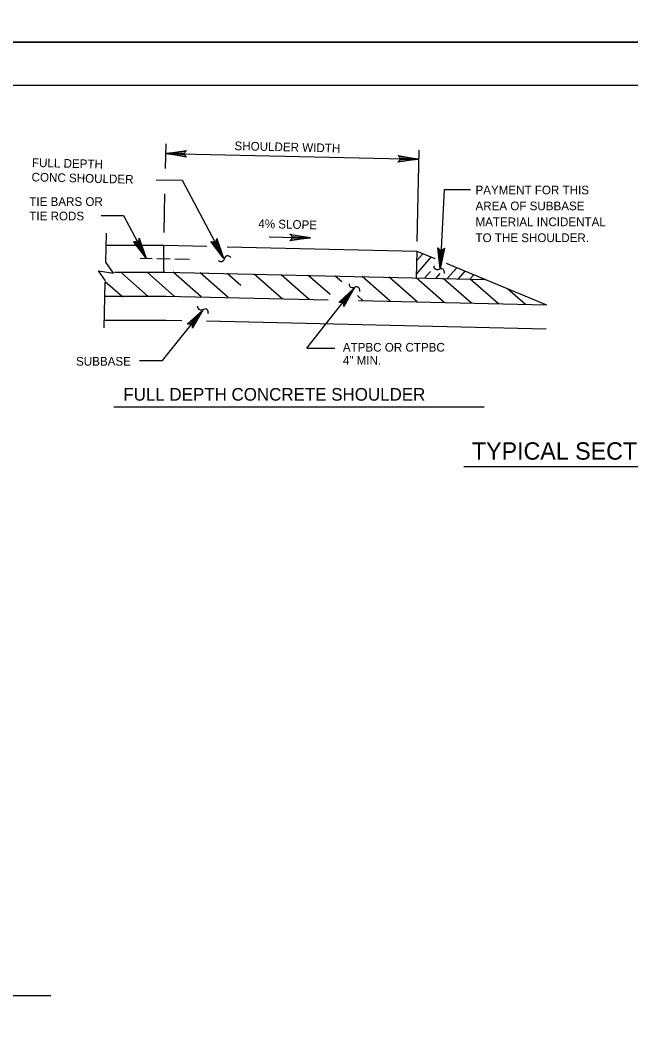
# Model space of a CAD drawing. Extents: x 638216 to 639962, y 297510 to 299292.
# Drawn here: x 638606.1 to 638817, y 297758.8 to 298111.7 of the extents above; entities that cross this region are included whole.
import ezdxf

# ---------------------------------------------------------------- set-up
doc = ezdxf.new("R2010")
doc.units = 0
for name, color, linetype in [('1', 7, 'Continuous'), ('2', 7, 'Continuous'), ('3', 7, 'Continuous'), ('PLT-BNDY', 7, 'Continuous')]:
    doc.layers.add(name, color=color, linetype=linetype)

msp = doc.modelspace()

# ---------------------------------------------------------------- linework, layer by layer
at = {"layer": '1'}
for p, q in [((638656.27, 298060.6), (638656.47, 298069.04)), ((638656.39, 298065.79), (638743.74, 298063.74)), ((638743.2, 298035.35), (638743.94, 298066.92)), ((638662.03, 298056.48), (638676.31, 298029.54)), ((638655.75, 298038.39), (638656.06, 298051.84)), ((638752.61, 298053.26), (638751.15, 298025.85)), ((638641.73, 298044.32), (638649.55, 298029.56)), ((638635.63, 298028.05), (638635.87, 298038.2)), ((638743.13, 298031.97), (638742.91, 298022.75)), ((638742.94, 298024.03), (638748.11, 298029.91)), ((638743.05, 298028.7), (638745.18, 298031.12)), ((638753.58, 298022.5), (638756.9, 298026.27)), ((638650.31, 298016.32), (638641.19, 298024.34)), ((638659.3, 298016.41), (638649.99, 298024.6)), ((638668.63, 298016.19), (638658.94, 298024.71)), ((638677.96, 298015.97), (638668.27, 298024.5)), ((638682.29, 298020.15), (638677.6, 298024.28)), ((638696.62, 298015.53), (638686.93, 298024.06)), ((638705.95, 298015.32), (638696.27, 298023.84)), ((638713.11, 298017.02), (638705.6, 298023.62)), ((638717.16, 298021.44), (638714.93, 298023.4)), ((638733.95, 298014.66), (638724.26, 298023.19)), ((638743.28, 298014.44), (638733.59, 298022.97)), ((638752.61, 298014.23), (638742.92, 298022.75)), ((638745.75, 298022.68), (638747.78, 298024.99)), ((638749.66, 298022.59), (638751.15, 298024.28)), ((638757.5, 298022.41), (638759.82, 298025.06)), ((638761.41, 298022.32), (638762.75, 298023.84)), ((638635.1, 298005.52), (638635.47, 298021.3)), ((638641.52, 298016.07), (638635.47, 298021.38)), ((638705.06, 297998.48), (638721.49, 298019.18)), ((638761.95, 298014.01), (638752.26, 298022.53)), ((638771.28, 298013.79), (638761.59, 298022.31)), ((638765.33, 298022.23), (638765.68, 298022.63)), ((638724.62, 298014.88), (638722.63, 298016.62)), ((638780.61, 298013.57), (638774.44, 298019)), ((638655.26, 297994.16), (638669.14, 298011.65))]:
    msp.add_line(p, q, dxfattribs=at)
for points in [[(639041.88, 297525.24), (639041.88, 298089.24), (638255.88, 298089.24), (638255.88, 297525.24), (639041.88, 297525.24), (639041.88, 297551.6), (638841.88, 297551.6), (638841.88, 297616.28), (639041.88, 297616.28), (639041.88, 297645.24), (638841.88, 297645.24), (638841.88, 297525.24), (638920.69, 297525.24), (638920.69, 297551.6), (638920.69, 297525.24), (638997.69, 297525.24), (638997.69, 297551.6), (638997.69, 297539.28), (639041.88, 297539.28)], [(639041.88, 297525.24), (639041.88, 298089.24), (638255.88, 298089.24), (638255.88, 297525.24), (639041.88, 297525.24), (639041.88, 297551.6), (638841.88, 297551.6), (638841.88, 297616.28), (639041.88, 297616.28), (639041.88, 297645.24), (638841.88, 297645.24), (638841.88, 297525.24), (638920.69, 297525.24), (638920.69, 297551.6), (638920.69, 297525.24), (638997.69, 297525.24), (638997.69, 297551.6), (638997.69, 297539.28), (639041.88, 297539.28)], [(639041.88, 297525.24), (639041.88, 298089.24), (638255.88, 298089.24), (638255.88, 297525.24), (639041.88, 297525.24), (639041.88, 297551.6), (638841.88, 297551.6), (638841.88, 297616.28), (639041.88, 297616.28), (639041.88, 297645.24), (638841.88, 297645.24), (638841.88, 297525.24), (638920.69, 297525.24), (638920.69, 297551.6), (638920.69, 297525.24), (638997.69, 297525.24), (638997.69, 297551.6), (638997.69, 297539.28), (639041.88, 297539.28)], [(638663.18, 298064.77), (638662.94, 298065.27), (638656.39, 298065.79), (638663.18, 298064.77), (638663.52, 298064.46), (638656.39, 298065.79), (638662.95, 298065.96), (638663.2, 298066.44), (638656.39, 298065.79), (638663.57, 298066.76), (638663.2, 298066.44)], [(638736.95, 298064.76), (638737.2, 298064.26), (638743.74, 298063.74), (638736.95, 298064.76), (638736.61, 298065.07), (638743.74, 298063.74), (638737.19, 298063.57), (638736.94, 298063.09), (638743.74, 298063.74), (638736.56, 298062.77), (638736.94, 298063.09)], [(638699.61, 298037.58), (638699.86, 298037.08), (638706.4, 298036.57), (638699.61, 298037.58), (638699.27, 298037.89), (638706.4, 298036.57), (638699.85, 298036.4), (638699.59, 298035.91), (638706.4, 298036.57), (638699.22, 298035.6), (638699.59, 298035.91)], [(638647.12, 298035.98), (638646.8, 298035.52), (638649.55, 298029.56), (638647.12, 298035.98), (638647.22, 298036.43), (638649.55, 298029.56), (638646.2, 298035.2), (638645.65, 298035.18), (638649.55, 298029.56), (638645.19, 298035.35), (638645.65, 298035.18)], [(638673.87, 298035.96), (638673.56, 298035.5), (638676.31, 298029.54), (638673.87, 298035.96), (638673.97, 298036.41), (638676.31, 298029.54), (638672.95, 298035.18), (638672.41, 298035.16), (638676.31, 298029.54), (638671.95, 298035.33), (638672.41, 298035.16)], [(638752.36, 298032.66), (638751.85, 298032.43), (638751.14, 298025.9), (638752.36, 298032.66), (638752.68, 298032.99), (638751.14, 298025.9), (638751.17, 298032.46), (638750.69, 298032.73), (638751.14, 298025.9), (638750.39, 298033.12), (638750.69, 298032.73)], [(638635.52, 298021.76), (638633.08, 298025.18), (638638.35, 298024.36), (638635.6, 298028.15)], [(638716.59, 298014.37), (638717.13, 298014.27), (638721.49, 298019.18), (638716.59, 298014.37), (638716.14, 298014.29), (638721.49, 298019.18), (638717.67, 298013.84), (638717.91, 298013.35), (638721.49, 298019.18), (638717.93, 298012.86), (638717.91, 298013.35)], [(638664.23, 298006.84), (638664.78, 298006.74), (638669.14, 298011.65), (638664.23, 298006.84), (638663.78, 298006.76), (638669.14, 298011.65), (638665.32, 298006.31), (638665.55, 298005.82), (638669.14, 298011.65), (638665.58, 298005.33), (638665.55, 298005.82)]]:
    msp.add_lwpolyline(points, dxfattribs=at)
at = {"layer": '2'}
for p, q in [((638653.08, 298056.69), (638662.03, 298056.48)), ((638752.61, 298053.26), (638761.68, 298053.26)), ((638634.04, 298044.32), (638641.73, 298044.32)), ((638692.11, 298036.9), (638706.4, 298036.57)), ((638636.01, 298034.05), (638655.65, 298034.02)), ((638655.73, 298024.78), (638655.65, 298034.02)), ((638655.65, 298034.02), (638670.53, 298033.67)), ((638677.53, 298033.51), (638743.13, 298031.97)), ((638743.13, 298031.97), (638749.29, 298029.42)), ((638647.53, 298029.61), (638651.61, 298029.51)), ((638653.28, 298029.47), (638657.85, 298029.37)), ((638659.53, 298029.33), (638664.5, 298029.21)), ((638753.19, 298027.8), (638787.95, 298013.4)), ((638638.61, 298024.78), (638656.18, 298024.78)), ((638656.18, 298024.78), (638766.73, 298022.19)), ((638635.33, 298016.47), (638656.42, 298016.49)), ((638656.42, 298016.49), (638712.46, 298015.18)), ((638722.98, 298014.92), (638787.95, 298013.4)), ((638635.34, 298008.18), (638656.42, 298008.2)), ((638656.42, 298008.2), (638661.92, 298008.07)), ((638670.4, 298007.86), (638787.76, 298005.11)), ((638705.06, 297998.48), (638714.79, 297998.48)), ((638647.3, 297994.16), (638655.26, 297994.16)), ((638638.36, 297978.23), (638766.33, 297978.23)), ((638759.31, 297957.54), (638860.47, 297957.54)), ((638464.47, 297774.7), (638616.64, 297774.7))]:
    msp.add_line(p, q, dxfattribs=at)
for points in [[(638678.87, 298029.83), (638678.41, 298030.17), (638677.42, 298030.38), (638676.74, 298029.83), (638676.57, 298029.2), (638676.13, 298028.56), (638675.31, 298028.31), (638674.99, 298028.41), (638674.55, 298028.77)], [(638752.65, 298024.26), (638752.62, 298024.83), (638752.15, 298025.73), (638751.29, 298025.9), (638750.69, 298025.63), (638749.92, 298025.55), (638749.21, 298026.02), (638749.08, 298026.34), (638749.07, 298026.9)], [(638723.44, 298018.02), (638723.41, 298018.59), (638722.94, 298019.49), (638722.08, 298019.66), (638721.48, 298019.38), (638720.71, 298019.31), (638720, 298019.78), (638719.87, 298020.09), (638719.86, 298020.65)], [(638671.07, 298010.36), (638671.03, 298010.93), (638670.56, 298011.83), (638669.71, 298012), (638669.11, 298011.73), (638668.34, 298011.65), (638667.63, 298012.12), (638667.49, 298012.44), (638667.49, 298013)]]:
    msp.add_spline(points, degree=3, dxfattribs=at)
at = {"layer": 'PLT-BNDY'}
for points in [[(638215.88, 298698.24), (639056.88, 298698.24), (639056.88, 298104.24), (638215.88, 298104.24)], [(638215.88, 298104.24), (639056.88, 298104.24), (639056.88, 297510.24), (638215.88, 297510.24)]]:
    msp.add_lwpolyline(points, close=True, dxfattribs=at)

# ---------------------------------------------------------------- texts
at = {"layer": '1'}
for s, rotation, p in [('SHOULDER WIDTH', 358.6615, (638680.08, 298066.91)), ('FULL DEPTH', 358.6605, (638610.09, 298061.12)), ('CONC SHOULDER', 358.6605, (638609.97, 298056.12)), ('4% SLOPE', 358.6615, (638688.3, 298040.02))]:
    msp.add_text(s, height=3, rotation=rotation, dxfattribs=at).set_placement(p)
for s, p in [('PAYMENT FOR THIS ', (638763.37, 298051.63)), ('TIE BARS OR', (638609.2, 298047.63)), ('AREA OF SUBBASE ', (638763.37, 298046.13)), ('TIE RODS', (638609.2, 298042.63)), ('MATERIAL INCIDENTAL', (638763.37, 298040.63)), ('TO THE SHOULDER.', (638763.37, 298035.13)), ('SUBBASE', (638625.35, 297992.42))]:
    msp.add_text(s, height=3, dxfattribs=at).set_placement(p)
at = {"layer": '3'}
for s, height, p in [('ATPBC OR CTPBC', 3, (638717.55, 297997.28)), ('4" MIN.', 3, (638717.55, 297992.78)), ('FULL DEPTH CONCRETE SHOULDER', 4.375, (638641.69, 297980.32)), ('TYPICAL SECTIONS', 6, (638762.15, 297959.93))]:
    msp.add_text(s, height=height, dxfattribs=at).set_placement(p)

doc.saveas('drawing.dxf')
